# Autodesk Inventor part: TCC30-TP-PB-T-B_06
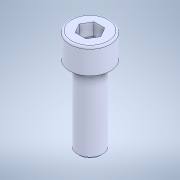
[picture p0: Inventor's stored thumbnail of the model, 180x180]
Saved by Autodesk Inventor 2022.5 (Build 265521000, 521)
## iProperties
Created: 2023-09
Part Number: TCC30-TP-PB-T-B_06
Material: 一般
Document SubType Name: Modeling
Designer: ImaoCorp
Density: 1 g/cm^3
Appearance: 既定
Author: ImaoCorp
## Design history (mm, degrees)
feature "TCC30-TP-PB-T-B_06"
node "ソリッド1"
